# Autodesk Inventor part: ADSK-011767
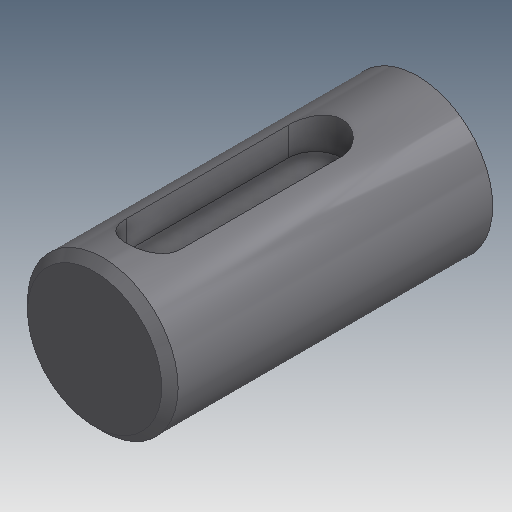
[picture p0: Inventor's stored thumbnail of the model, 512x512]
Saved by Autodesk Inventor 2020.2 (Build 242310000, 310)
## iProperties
Created: 1999-12
Part Number: ADSK-011767
Material: Acier doux
Document SubType Name: Modeling
Designer: tgregory
Density: 7.86 g/cm^3
Appearance: Metal-Steel(Polish)
Mass: 33.9802 g
Surface Area: 17.2856 cm^2
Volume: 4.32318 cm^3
Control State: 0
Checked Out: False
Master: False
Shininess: 0.0
Length Units: 11272
Angle Units: 11279
Time Units: 11290
Mass Units: 11286
Length Display Precision: 3
Angle Display Precision: 2
Compacted: True
Dimensions: 0,6x1,2x0,6 in
Mass: 0,075 lb
VLT_Material: Acier doux
Density: 0.0
Volumn: 0.0
Area: 0.0
PropertySet Name: Model Information
Author: tgregory
Revision Number: -
Title: ADSK-011767
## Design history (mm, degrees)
node "Extrusion1" dims "d3" = 29.99994, "d4" = 0
node "Chamfer1" dims "d5" = 0.762, "d6" = 0.762, "d15" = 45 deg
workplane "Work Plane1"
node "Extrusion2" dims "d12" = 6.1976, "d13" = 0
node "Solide1"
node "Corps solides"
node "Corps surfaciques"
sketch "Sketch1"
  geometry: C1 r 6.998 at (0, 0); 1 further point
  constraints: 1 centre point, 1 coincident
  dimensions: "d0" = 13.9954 diameter of C1
sketch "Sketch2"
  geometry: L1 (34.761, 30)-(-34.761, 30); L2 (0, 30)-(0, 1.944); L3 (0, 24.501)-(-36.881, 24.501); L4 (-0.001, 9.5)-(-36.881, 9.5); L5 (2.499, 30)-(2.499, 1.944); L6 (-2.502, 30)-(-2.502, 1.944); L7 (2.499, 9.5)-(2.499, 24.501); L8 (-2.502, 9.5)-(-2.495, 24.352); L9 (-6.236, 30)-(6.236, 30) reference; L10 (0, -0.862)-(0, 38.417) reference; A1 r 2.499 centre (0, 24.501) between (2.499, 24.501) and (-2.495, 24.352); A2 r 2.501 centre (-0.001, 9.5) between (-2.502, 9.5) and (2.499, 9.5)
  constraints: 16 end point, 5 point on line, 4 point on circle, 2 centre point, 2 coincident, 2 collinear, 2 perpendicular, 2 tangent, 1 midpoint
  dimensions: "d8" = 5.4991 vertical distance of L3.end L1.end; "d9" = 15.00124 distance between parallel lines of L4 L3; "d10" = 2.49936 distance between parallel lines of L5 L2; "d11" = 5.00126 distance between parallel lines of L6 L5
other parameters: "d7" = 6.9977 (= 0.5 x d0)
